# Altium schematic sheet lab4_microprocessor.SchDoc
size A4; Author: Michał Wojna; CompanyName: AGH; Revision: 1; SheetNumber: 3; SheetTotal: 3
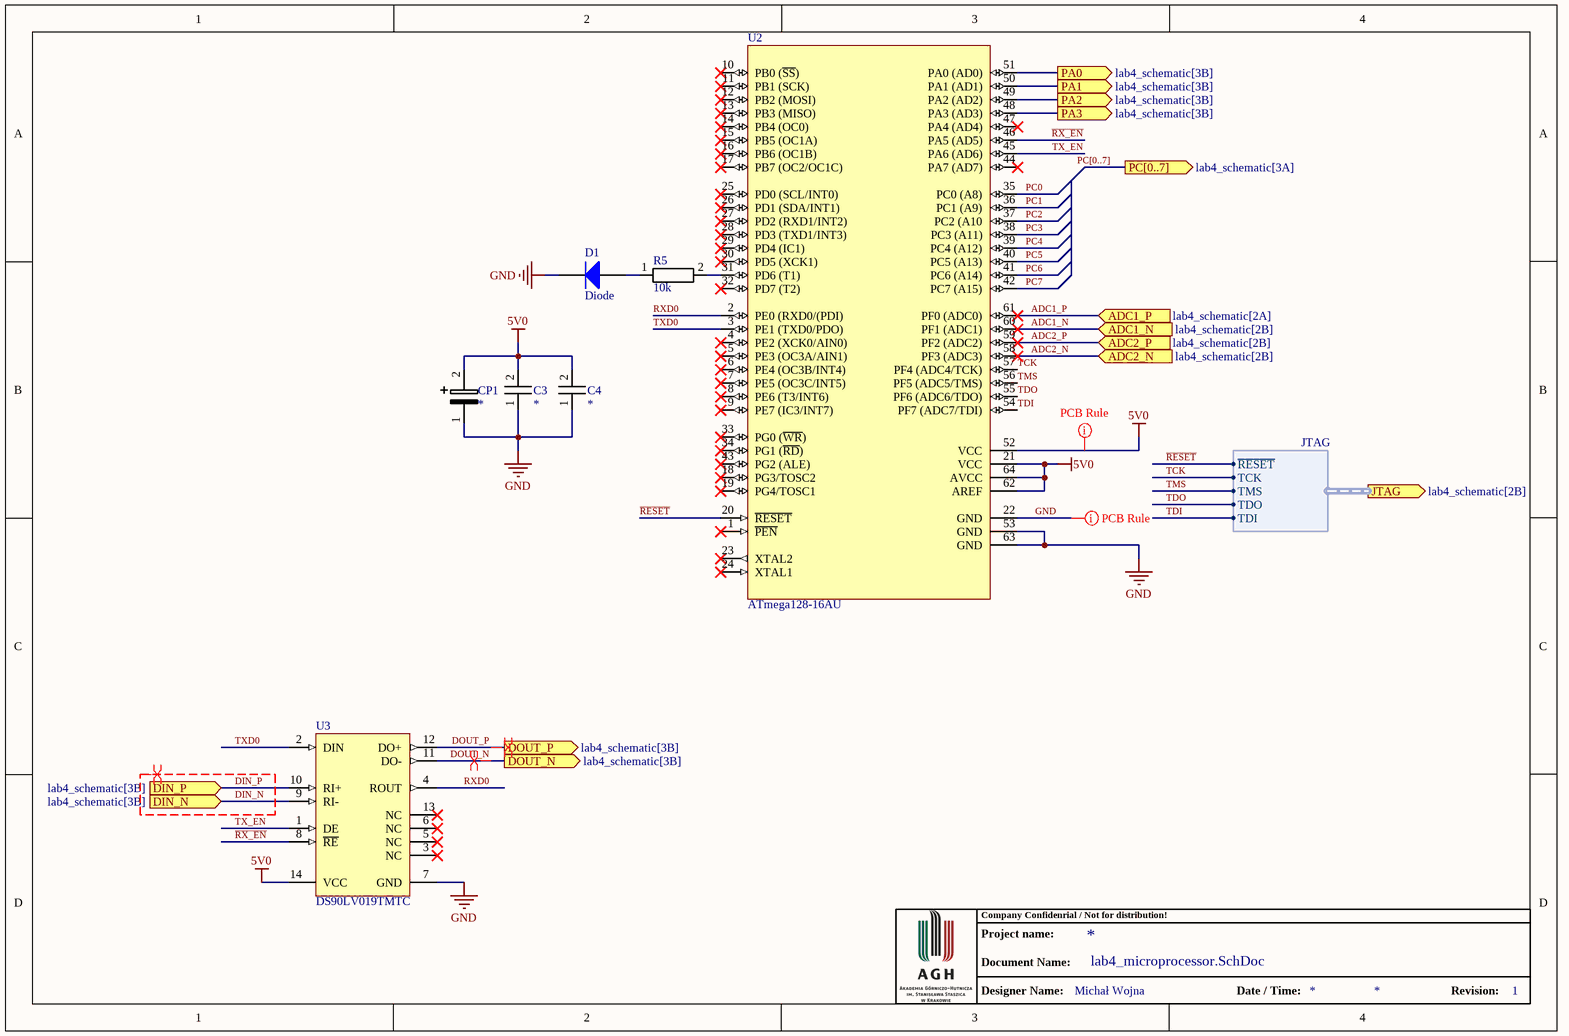
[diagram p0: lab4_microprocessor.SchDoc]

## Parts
C3  *  [0805_STD]
C4  *  [0805_STD]
CP1  *  [VJ_Tantalum_D]
D1  Diode  [SMC]
R5  10k  [0603]
U2  ATmega128-16AU  [64A_M]
U3  DS90LV019TMTC  [PW0014A_L]

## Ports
ADC1_N (in, see lab4_schematic[2B]), ADC1_P (in, see lab4_schematic[2A]), ADC2_N (in, see lab4_schematic[2B]), ADC2_P (in, see lab4_schematic[2B]), DIN_N (in, see lab4_schematic[3B]), DIN_P (in, see lab4_schematic[3B]), DOUT_N (out, see lab4_schematic[3B]), DOUT_P (out, see lab4_schematic[3B]), JTAG (out, harness JTAG, see lab4_schematic[2B]), PA0 (out, see lab4_schematic[3B]), PA1 (out, see lab4_schematic[3B]), PA2 (out, see lab4_schematic[3B]), PA3 (out, see lab4_schematic[3B]), PC[0..7] (out, see lab4_schematic[3A])

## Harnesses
JTAG: ~{RESET}, TCK, TMS, TDO, TDI

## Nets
5V0: C3.2(PIN) C4.2(PIN) CP1.2(PIN) U2.21(VCC) U2.52(VCC) U2.62(AREF) U2.64(AVCC) U3.14(VCC)
GND: C3.1(PIN) C4.1(PIN) CP1.1(PIN) D1.2(K) U2.22(GND) U2.53(GND) U2.63(GND) U3.7(GND)
~{RESET}: U2.20(~{RESET}) ; port JTAG.~{RESET}
ADC1_N: U2.60(PF1_(ADC1)) ; port ADC1_N
ADC1_P: U2.61(PF0_(ADC0)) ; port ADC1_P
ADC2_N: U2.58(PF3_(ADC3)) ; port ADC2_N
ADC2_P: U2.59(PF2_(ADC2)) ; port ADC2_P
DIN_N: U3.9(RI-) ; port DIN_N
DIN_P: U3.10(RI+) ; port DIN_P
DOUT_N: U3.11(DO-) ; port DOUT_N
DOUT_P: U3.12(DO+) ; port DOUT_P
PA0: U2.51(PA0_(AD0)) ; port PA0
PA1: U2.50(PA1_(AD1)) ; port PA1
PA2: U2.49(PA2_(AD2)) ; port PA2
PA3: U2.48(PA3_(AD3)) ; port PA3
PC0: U2.35(PC0_(A8))
PC1: U2.36(PC1_(A9))
PC2: U2.37(PC2_(A10)
PC3: U2.38(PC3_(A11))
PC4: U2.39(PC4_(A12))
PC5: U2.40(PC5_(A13))
PC6: U2.41(PC6_(A14))
PC7: U2.42(PC7_(A15))
~{RX_EN}: U2.46(PA5_(AD5)) U3.8(~{RE})
RXD0: U2.2(PE0_(RXD0/(PDI)) U3.4(ROUT)
TCK: U2.57(PF4_(ADC4/TCK)) ; port JTAG.TCK
TDI: U2.54(PF7_(ADC7/TDI)) ; port JTAG.TDI
TDO: U2.55(PF6_(ADC6/TDO)) ; port JTAG.TDO
TMS: U2.56(PF5_(ADC5/TMS)) ; port JTAG.TMS
TX_EN: U2.45(PA6_(AD6)) U3.1(DE)
TXD0: U2.3(PE1_(TXD0/PDO)) U3.2(DIN)
NetD1_1: D1.1(A) R5.1(PIN)
NetR5_2: R5.2(PIN) U2.31(PD6_(T1))

Not connected (* = marked no-connect by the designer): U2 1(~{PEN})* 4(PE2_(XCK0/AIN0))* 5(PE3_(OC3A/AIN1))* 6(PE4_(OC3B/INT4))* 7(PE5_(OC3C/INT5))* 8(PE6_(T3/INT6))* 9(PE7_(IC3/INT7))* 10(PB0_(~{SS}))* 11(PB1_(SCK))* 12(PB2_(MOSI))* 13(PB3_(MISO))* 14(PB4_(OC0))* 15(PB5_(OC1A))* 16(PB6_(OC1B))* 17(PB7_(OC2/OC1C))* 18(PG3/TOSC2)* 19(PG4/TOSC1)* 23(XTAL2)* 24(XTAL1)* 25(PD0_(SCL/INT0))* 26(PD1_(SDA/INT1))* 27(PD2_(RXD1/INT2))* 28(PD3_(TXD1/INT3))* 29(PD4_(IC1))* 30(PD5_(XCK1))* 32(PD7_(T2))* 33(PG0_(~{WR}))* 34(PG1_(~{RD}))* 43(PG2_(ALE))* 44(PA7_(AD7))* 47(PA4_(AD4))*; U3 3(NC)* 5(NC)* 6(NC)* 13(NC)*

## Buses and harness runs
bus PC[0..7] = port PC[0..7]

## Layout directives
rule Width Constraint [Pref Width = 20mil    Min Width = 15mil    Max Width = 50mil]: 5V0, GND
differential pair: DIN_N, DIN_P, DOUT_N, DOUT_P

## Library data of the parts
C3 C4 = Capacitor
CP1 = Capacitor_polarized
D1 = Diode: Default Diode
R5 = Resistor
U2 = CMP-0095-00259-2: 8-bit AVR Microcontroller, 4.5-5.5V, 128KB Flash, 4KB EEPROM, 4KB SRAM, 64-pin TQFP, Industrial Grade (-40°C to 85°C)
U3 = CMP-0058-01150-3: 3.3V or 5V LVDS Driver/Receiver, 14-pin TSSOP; Manufacturer: Texas Instruments; PackageTopMarking: NSZXYTT*LV019T*MTC; PowerWise: N; CompType: Interface IC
